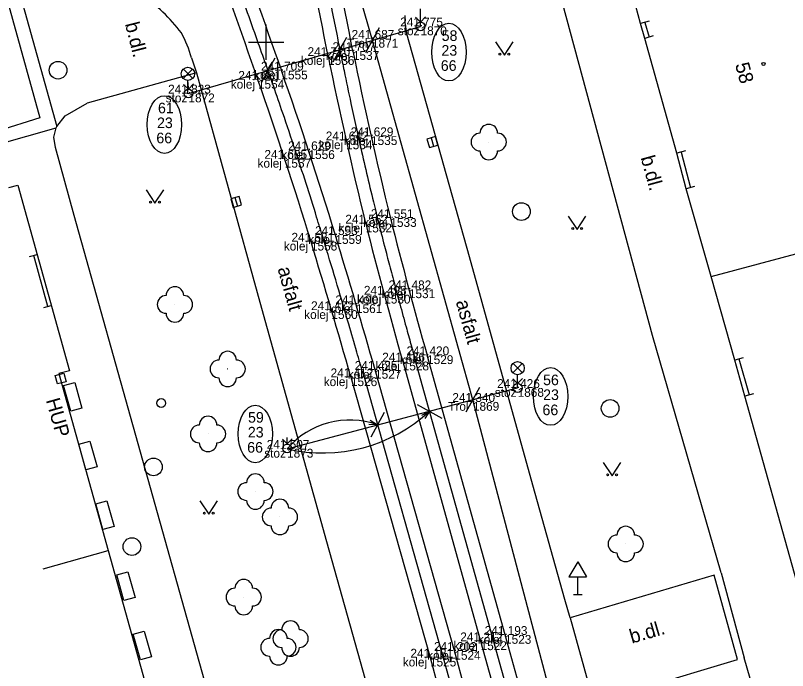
# Model space of a CAD drawing. Extents: x -599098 to -598820, y -1159597 to -1158744.
# Drawn here: x -599064.19 to -599020.49, y -1158835.58 to -1158798.48 of the extents above; entities that cross this region are included whole.
import ezdxf

# ---------------------------------------------------------------- set-up
doc = ezdxf.new("R2010")
doc.units = 0
for name, color, linetype in [('body', 7, 'Continuous'), ('budovy', 7, 'Continuous'), ('dopravní značky semafory', 7, 'Continuous'), ('druh pozemku stromy', 7, 'Continuous'), ('hektometrická síť', 7, 'Continuous'), ('kresba', 7, 'Continuous'), ('kódy bodů', 7, 'Continuous'), ('popisy', 7, 'Continuous'), ('popisy budov', 7, 'Continuous'), ('tram_koleje', 7, 'Continuous'), ('tram_osa', 7, 'Continuous'), ('trol_detaily', 7, 'Continuous'), ('trol_převěsy', 7, 'Continuous'), ('trol_troljová stopa', 7, 'Continuous'), ('trol_ved sloupy konzoly', 7, 'Continuous'), ('trol_čísla sloupů', 7, 'Continuous'), ('výšky bodů', 7, 'Continuous'), ('značky IS', 7, 'Continuous'), ('čísla bodů', 7, 'Continuous')]:
    doc.layers.add(name, color=color, linetype=linetype)

msp = doc.modelspace()

# ---------------------------------------------------------------- linework, layer by layer
at = {"layer": 'body'}
for p, q in [((-599041.262, -1158799.101), (-599041.262, -1158799.101)), ((-599044.013, -1158799.804), (-599044.013, -1158799.804)), ((-599045.09, -1158800.499), (-599045.09, -1158800.499)), ((-599046.492, -1158800.781), (-599046.492, -1158800.781)), ((-599049.138, -1158801.601), (-599049.138, -1158801.601)), ((-599050.466, -1158802.126), (-599050.466, -1158802.126)), ((-599054.399, -1158802.902), (-599054.399, -1158802.902)), ((-599044.063, -1158805.318), (-599044.063, -1158805.318)), ((-599045.476, -1158805.555), (-599045.476, -1158805.555)), ((-599047.604, -1158806.111), (-599047.604, -1158806.111)), ((-599048.947, -1158806.6), (-599048.947, -1158806.6)), ((-599044.368, -1158810.268), (-599044.368, -1158810.268)), ((-599042.97, -1158809.955), (-599042.97, -1158809.955)), ((-599046.082, -1158810.917), (-599046.082, -1158810.917)), ((-599047.462, -1158811.292), (-599047.462, -1158811.292)), ((-599041.921, -1158813.989), (-599041.921, -1158813.989)), ((-599043.318, -1158814.296), (-599043.318, -1158814.296)), ((-599044.915, -1158814.833), (-599044.915, -1158814.833)), ((-599046.306, -1158815.169), (-599046.306, -1158815.169)), ((-599040.891, -1158817.723), (-599040.891, -1158817.723)), ((-599042.271, -1158818.081), (-599042.271, -1158818.081)), ((-599043.835, -1158818.553), (-599043.835, -1158818.553)), ((-599045.202, -1158818.97), (-599045.202, -1158818.97)), ((-599035.767, -1158819.577), (-599035.767, -1158819.577)), ((-599038.296, -1158820.367), (-599038.296, -1158820.367)), ((-599048.818, -1158823.02), (-599048.818, -1158823.02)), ((-599037.862, -1158833.921), (-599037.862, -1158833.921)), ((-599036.478, -1158833.562), (-599036.478, -1158833.562)), ((-599039.348, -1158834.467), (-599039.348, -1158834.467)), ((-599040.727, -1158834.846), (-599040.727, -1158834.846))]:
    msp.add_line(p, q, dxfattribs=at)
at = {"layer": 'budovy'}
for p, q in [((-599028.81, -1158798.94), (-599029.62, -1158795.96)), ((-599028.57, -1158799.78), (-599028.81, -1158798.94)), ((-599026.75, -1158806.28), (-599028.57, -1158799.78)), ((-599026.23, -1158808.3), (-599026.75, -1158806.28)), ((-599064.56, -1158808.22), (-599064.06, -1158808.09)), ((-599064.06, -1158808.09), (-599061.14, -1158818.6)), ((-599024.82, -1158813.26), (-599026.23, -1158808.3)), ((-599024.82, -1158813.26), (-599018.089, -1158811.461)), ((-599023.48, -1158818), (-599024.82, -1158813.26)), ((-599022.9, -1158820.04), (-599023.48, -1158818)), ((-599061.14, -1158818.6), (-599061.73, -1158818.75)), ((-599061.73, -1158818.75), (-599058.94, -1158828.78)), ((-599019.84, -1158831.02), (-599022.9, -1158820.04)), ((-599062.618, -1158829.815), (-599058.94, -1158828.78)), ((-599058.94, -1158828.78), (-599054.26, -1158845.47))]:
    msp.add_line(p, q, dxfattribs=at)
msp.add_circle((-599021.85, -1158801.23), 0.0875, dxfattribs=at)
at = {"layer": 'dopravní značky semafory'}
for p, q in [((-599041.262, -1158799.101), (-599041.262, -1158798.101)), ((-599032.36, -1158829.414), (-599032.86, -1158830.28)), ((-599032.36, -1158829.414), (-599031.86, -1158830.28)), ((-599032.86, -1158830.28), (-599031.86, -1158830.28)), ((-599032.36, -1158831.28), (-599032.36, -1158830.28)), ((-599032.61, -1158831.28), (-599032.11, -1158831.28))]:
    msp.add_line(p, q, dxfattribs=at)
at = {"layer": 'druh pozemku stromy'}
for points in [[(-599037.018, -1158799.976), (-599036.518, -1158800.726), (-599036.018, -1158799.976)], [(-599056.795, -1158808.355), (-599056.295, -1158809.105), (-599055.795, -1158808.355)], [(-599032.897, -1158809.846), (-599032.397, -1158810.596), (-599031.897, -1158809.846)], [(-599030.922, -1158823.795), (-599030.422, -1158824.545), (-599029.922, -1158823.795)], [(-599053.749, -1158825.967), (-599053.249, -1158826.717), (-599052.749, -1158825.967)]]:
    msp.add_lwpolyline(points, dxfattribs=at)
for centre, radius in [((-599036.768, -1158800.676), 0.05), ((-599036.268, -1158800.676), 0.05), ((-599037.4, -1158805.65), 0.0005), ((-599056.545, -1158809.055), 0.05), ((-599056.045, -1158809.055), 0.05), ((-599032.647, -1158810.546), 0.05), ((-599032.147, -1158810.546), 0.05), ((-599055.167, -1158814.847), 0.0005), ((-599052.18, -1158818.5), 0.0005), ((-599053.29, -1158822.18), 0.0005), ((-599030.672, -1158824.495), 0.05), ((-599030.172, -1158824.495), 0.05), ((-599050.61, -1158825.44), 0.0005), ((-599053.499, -1158826.667), 0.05), ((-599052.999, -1158826.667), 0.05), ((-599049.22, -1158826.88), 0.0005), ((-599029.65, -1158828.41), 0.0005), ((-599051.27, -1158831.42), 0.0005), ((-599048.62, -1158833.77), 0.0005), ((-599049.31, -1158834.26), 0.0005)]:
    msp.add_circle(centre, radius, dxfattribs=at)
for centre, start, end in [((-599037.4, -1158805.15), 0, 180), ((-599037.9, -1158805.65), 90, 270), ((-599036.9, -1158805.65), 270, 90), ((-599037.4, -1158806.15), 180, 360), ((-599055.167, -1158814.347), 0, 180), ((-599055.667, -1158814.847), 90, 270), ((-599054.667, -1158814.847), 270, 90), ((-599055.167, -1158815.347), 180, 360), ((-599052.18, -1158818), 0, 180), ((-599052.68, -1158818.5), 90, 270), ((-599051.68, -1158818.5), 270, 90), ((-599052.18, -1158819), 180, 360), ((-599053.29, -1158821.68), 0, 180), ((-599053.79, -1158822.18), 90, 270), ((-599052.79, -1158822.18), 270, 90), ((-599053.29, -1158822.68), 180, 360), ((-599050.61, -1158824.94), 0, 180), ((-599051.11, -1158825.44), 90, 270), ((-599050.11, -1158825.44), 270, 90), ((-599050.61, -1158825.94), 180, 360), ((-599049.22, -1158826.38), 0, 180), ((-599049.72, -1158826.88), 90, 270), ((-599048.72, -1158826.88), 270, 90), ((-599049.22, -1158827.38), 180, 360), ((-599029.65, -1158827.91), 0, 180), ((-599030.15, -1158828.41), 90, 270), ((-599029.15, -1158828.41), 270, 90), ((-599029.65, -1158828.91), 180, 360), ((-599051.27, -1158830.92), 0, 180), ((-599051.77, -1158831.42), 90, 270), ((-599050.77, -1158831.42), 270, 90), ((-599051.27, -1158831.92), 180, 360), ((-599048.62, -1158833.27), 0, 180), ((-599049.31, -1158833.76), 0, 180), ((-599049.12, -1158833.77), 90, 270), ((-599048.12, -1158833.77), 270, 90), ((-599049.81, -1158834.26), 90, 270), ((-599048.81, -1158834.26), 270, 90), ((-599048.62, -1158834.27), 180, 360), ((-599049.31, -1158834.76), 180, 360)]:
    msp.add_arc(centre, 0.5, start, end, dxfattribs=at)
at = {"layer": 'hektometrická síť'}
for p, q in [((-599050, -1158801), (-599050, -1158799)), ((-599051, -1158800), (-599049, -1158800))]:
    msp.add_line(p, q, dxfattribs=at)
at = {"layer": 'kresba'}
for p, q in [((-599064.94, -1158796.55), (-599062.82, -1158804.27)), ((-599064.18, -1158796.38), (-599061.85, -1158804.77)), ((-599028.14, -1158816.61), (-599033.21, -1158797.85)), ((-599028.329, -1158798.803), (-599028.81, -1158798.94)), ((-599028.57, -1158798.871), (-599028.33, -1158799.711)), ((-599038.5, -1158812.15), (-599042.04, -1158799.52)), ((-599028.089, -1158799.643), (-599028.57, -1158799.78)), ((-599054.23, -1158800.89), (-599053.94, -1158801.73)), ((-599053.94, -1158801.73), (-599060.14, -1158803.45)), ((-599053.94, -1158801.73), (-599050.36, -1158814.72)), ((-599061.37, -1158804.16), (-599060.139, -1158803.454)), ((-599061.85, -1158804.77), (-599061.37, -1158804.16)), ((-599062.82, -1158804.27), (-599065.48, -1158805.11)), ((-599065.27, -1158805.8), (-599061.89, -1158804.85)), ((-599062.02, -1158805.38), (-599061.89, -1158804.85)), ((-599061.89, -1158804.85), (-599061.85, -1158804.77)), ((-599061.93, -1158805.96), (-599062.02, -1158805.38)), ((-599060.87, -1158809.81), (-599061.93, -1158805.96)), ((-599026.266, -1158806.155), (-599026.75, -1158806.28)), ((-599026.508, -1158806.218), (-599025.988, -1158808.238)), ((-599025.746, -1158808.175), (-599026.23, -1158808.3)), ((-599052.85, -1158838.43), (-599060.87, -1158809.81)), ((-599063.397, -1158812.133), (-599062.97, -1158812.014)), ((-599062.351, -1158814.956), (-599063.156, -1158812.066)), ((-599034.9, -1158825.08), (-599038.5, -1158812.15)), ((-599062.592, -1158815.023), (-599062.167, -1158814.905)), ((-599050.36, -1158814.72), (-599046.59, -1158828.27)), ((-599024.24, -1158830.05), (-599028.14, -1158816.61)), ((-599022.999, -1158817.863), (-599023.48, -1158818)), ((-599023.24, -1158817.932), (-599022.66, -1158819.972)), ((-599061.47, -1158819.43), (-599060.84, -1158819.26)), ((-599061.06, -1158820.89), (-599061.47, -1158819.43)), ((-599060.84, -1158819.26), (-599060.43, -1158820.72)), ((-599022.419, -1158819.903), (-599022.9, -1158820.04)), ((-599060.43, -1158820.72), (-599061.06, -1158820.89)), ((-599060.61, -1158822.76), (-599059.98, -1158822.59)), ((-599060.2, -1158824.22), (-599060.61, -1158822.76)), ((-599059.98, -1158822.59), (-599059.57, -1158824.05)), ((-599059.57, -1158824.05), (-599060.2, -1158824.22)), ((-599033.1, -1158831.56), (-599034.9, -1158825.08)), ((-599059.65, -1158826.13), (-599059.02, -1158825.96)), ((-599059.02, -1158825.96), (-599058.61, -1158827.42)), ((-599059.24, -1158827.59), (-599059.65, -1158826.13)), ((-599058.61, -1158827.42), (-599059.24, -1158827.59)), ((-599046.59, -1158828.27), (-599042.83, -1158841.62)), ((-599058.46, -1158830.16), (-599057.83, -1158829.99)), ((-599057.83, -1158829.99), (-599057.42, -1158831.45)), ((-599058.05, -1158831.62), (-599058.46, -1158830.16)), ((-599024.64, -1158830.17), (-599032.79, -1158832.59)), ((-599023.33, -1158834.96), (-599024.64, -1158830.17)), ((-599024.24, -1158830.05), (-599022.94, -1158834.85)), ((-599057.42, -1158831.45), (-599058.05, -1158831.62)), ((-599032.79, -1158832.59), (-599033.1, -1158831.56)), ((-599032.79, -1158832.59), (-599031.46, -1158837.38)), ((-599057.53, -1158833.51), (-599056.9, -1158833.34)), ((-599057.12, -1158834.97), (-599057.53, -1158833.51)), ((-599056.9, -1158833.34), (-599056.49, -1158834.8)), ((-599056.49, -1158834.8), (-599057.12, -1158834.97)), ((-599031.46, -1158837.38), (-599023.33, -1158834.96)), ((-599020.59, -1158843.13), (-599022.94, -1158834.85))]:
    msp.add_line(p, q, dxfattribs=at)
for centre, radius, start, end in [((-599062.719, -1158805.456), 9.927, 37.0843, 55.2434), ((-599038.178, -1158798.547), 3.982, 179.0288, 194.1351), ((-599060.224, -1158802.472), 6.2, 14.7823, 28.9596)]:
    msp.add_arc(centre, radius, start, end, dxfattribs=at)
at = {"layer": 'tram_koleje'}
for p, q in [((-599036.478, -1158833.562), (-599040.891, -1158817.723)), ((-599042.271, -1158818.081), (-599037.862, -1158833.921)), ((-599039.348, -1158834.467), (-599043.835, -1158818.553)), ((-599045.202, -1158818.97), (-599040.727, -1158834.846)), ((-599037.862, -1158833.921), (-599033.651, -1158849.046)), ((-599032.265, -1158848.671), (-599036.478, -1158833.562)), ((-599035.263, -1158849.128), (-599039.348, -1158834.467)), ((-599040.727, -1158834.846), (-599036.638, -1158849.522))]:
    msp.add_line(p, q, dxfattribs=at)
for centre, radius, start, end in [((-599536.84, -1158897.01), 501.131, 11.10372, 12.14061), ((-599529.595, -1158895.69), 492.338, 11.11461, 12.15891), ((-597210.712, -1158150.292), 1950.388, 199.246436, 199.507983), ((-597789.976, -1158353.746), 1337.864, 199.196739, 199.581422), ((-598824.298, -1158755.964), 225.239, 191.40389, 193.86919), ((-598821.824, -1158755.462), 229.194, 191.40431, 193.83485), ((-599267.683, -1158878.451), 231.664, 16.94892, 19.37397), ((-599269.435, -1158878.965), 232.059, 16.95482, 19.33652), ((-598780.621, -1158743.667), 272.026, 194.17207, 195.876), ((-598778.54, -1158743.346), 272.69, 194.13845, 195.82811), ((-599584.712, -1158973.565), 562.652, 15.99198, 16.80254), ((-599586.761, -1158974.205), 563.369, 15.99466, 16.80866)]:
    msp.add_arc(centre, radius, start, end, dxfattribs=at)
at = {"layer": 'tram_osa'}
for points in [[(-598998.482, -1158972.553), (-599001.612, -1158961.324), (-599004.755, -1158950.077), (-599007.858, -1158938.885), (-599009.243, -1158933.905), (-599010.468, -1158929.507), (-599013.278, -1158919.438), (-599013.649, -1158918.106), (-599016.803, -1158906.805), (-599019.981, -1158895.419), (-599022.632, -1158885.903), (-599025.83, -1158874.435), (-599028.989, -1158863.1), (-599032.097, -1158851.938), (-599032.958, -1158848.858), (-599037.17, -1158833.741), (-599041.581, -1158817.902)], [(-599044.518, -1158818.761), (-599040.037, -1158834.656), (-599035.95, -1158849.325), (-599035.019, -1158852.662), (-599031.892, -1158863.891), (-599028.72, -1158875.28), (-599025.529, -1158886.717), (-599022.874, -1158896.237), (-599019.714, -1158907.545), (-599016.534, -1158918.918), (-599016.338, -1158919.622), (-599013.47, -1158929.909), (-599012.317, -1158934.072), (-599010.723, -1158939.81), (-599007.63, -1158950.895), (-599004.503, -1158962.072), (-599001.36, -1158973.306)]]:
    msp.add_lwpolyline(points, dxfattribs=at)
for points in [[(-599050.226, -1158781.191), (-599049.779, -1158782.843), (-599049.26, -1158784.839), (-599048.908, -1158786.239), (-599048.459, -1158788.087), (-599047.812, -1158790.885), (-599047.609, -1158791.804), (-599047.116, -1158794.12), (-599046.807, -1158795.602), (-599046.534, -1158796.929), (-599046.277, -1158798.195), (-599045.991, -1158799.626), (-599045.791, -1158800.64), (-599045.594, -1158801.602), (-599045.202, -1158803.462), (-599044.904, -1158804.829), (-599044.69, -1158805.788), (-599044.317, -1158807.41), (-599043.931, -1158809.037), (-599043.782, -1158809.649), (-599043.669, -1158810.111), (-599043.304, -1158811.541), (-599043.022, -1158812.624), (-599042.724, -1158813.749), (-599042.438, -1158814.813), (-599042.08, -1158816.121), (-599041.806, -1158817.102), (-599041.581, -1158817.902)], [(-599044.518, -1158818.761), (-599044.868, -1158817.544), (-599045.327, -1158815.967), (-599045.725, -1158814.611), (-599046.408, -1158812.312), (-599046.772, -1158811.104), (-599047.143, -1158809.897), (-599047.745, -1158807.988), (-599048.359, -1158806.1), (-599049.061, -1158804.005), (-599049.575, -1158802.512), (-599050.57, -1158799.693), (-599051.212, -1158797.872), (-599051.881, -1158795.968), (-599052.492, -1158794.222), (-599053.195, -1158792.184), (-599053.706, -1158790.656), (-599054.07, -1158789.541), (-599054.412, -1158788.474), (-599055.062, -1158786.382), (-599055.575, -1158784.668), (-599055.829, -1158783.8), (-599056.112, -1158782.812)]]:
    msp.add_spline(points, degree=3, dxfattribs=at)
at = {"layer": 'trol_detaily'}
for p, q in [((-599043.606, -1158799.19), (-599044.376, -1158800.591)), ((-599045.448, -1158799.723), (-599046.219, -1158801.125)), ((-599049.512, -1158800.899), (-599050.282, -1158802.3)), ((-599037.926, -1158819.547), (-599038.696, -1158820.949)), ((-599041.449, -1158820.506), (-599040.048, -1158821.277)), ((-599043.313, -1158820.969), (-599044.083, -1158822.37)), ((-599041.198, -1158821.111), (-599040.749, -1158820.891)), ((-599040.749, -1158820.891), (-599041.028, -1158821.306)), ((-599043.698, -1158821.669), (-599044.197, -1158821.639)), ((-599044.115, -1158821.393), (-599043.698, -1158821.669))]:
    msp.add_line(p, q, dxfattribs=at)
for centre, radius, start, end in [((-599046.79, -1158814.349), 8.905, 256.8355, 312.7216), ((-599045.288, -1158826.02), 4.632, 69.9221, 139.635)]:
    msp.add_arc(centre, radius, start, end, dxfattribs=at)
at = {"layer": 'trol_převěsy'}
for p, q in [((-599054.399, -1158802.902), (-599041.262, -1158799.101)), ((-599048.818, -1158823.02), (-599035.767, -1158819.577))]:
    msp.add_line(p, q, dxfattribs=at)
at = {"layer": 'trol_troljová stopa'}
for p, q in [((-599043.991, -1158799.891), (-599045.552, -1158794.297)), ((-599038.311, -1158820.248), (-599043.991, -1158799.891)), ((-599032.143, -1158843.549), (-599038.311, -1158820.248))]:
    msp.add_line(p, q, dxfattribs=at)
at = {"layer": 'trol_ved sloupy konzoly'}
for p, q in [((-599041.265, -1158798.852), (-599041.271, -1158798.48)), ((-599041.265, -1158798.852), (-599041.54, -1158798.585)), ((-599041.265, -1158798.852), (-599040.979, -1158798.559)), ((-599054.402, -1158802.653), (-599054.677, -1158802.386)), ((-599054.402, -1158802.653), (-599054.408, -1158802.281)), ((-599054.402, -1158802.653), (-599054.116, -1158802.36)), ((-599035.77, -1158819.328), (-599036.045, -1158819.061)), ((-599035.77, -1158819.328), (-599035.776, -1158818.956)), ((-599035.77, -1158819.328), (-599035.484, -1158819.035)), ((-599048.809, -1158822.748), (-599049.084, -1158822.481)), ((-599048.809, -1158822.748), (-599048.815, -1158822.376)), ((-599048.809, -1158822.748), (-599048.523, -1158822.455))]:
    msp.add_line(p, q, dxfattribs=at)
for centre in [(-599041.261, -1158799.102), (-599054.398, -1158802.903), (-599035.766, -1158819.578), (-599048.805, -1158822.998)]:
    msp.add_circle(centre, 0.248, dxfattribs=at)
at = {"layer": 'trol_čísla sloupů'}
for centre in [(-599039.657, -1158800.559), (-599055.757, -1158804.659), (-599033.902, -1158820.057), (-599050.616, -1158822.178)]:
    msp.add_ellipse(centre, major_axis=(0, -1.633), ratio=0.595913, dxfattribs=at)
at = {"layer": 'značky IS'}
for p, q in [((-599054.693, -1158802.052), (-599054.165, -1158801.524)), ((-599054.157, -1158802.05), (-599054.685, -1158801.52)), ((-599054.429, -1158802.914), (-599054.429, -1158802.164)), ((-599040.658, -1158805.409), (-599040.522, -1158805.891)), ((-599051.768, -1158808.799), (-599051.632, -1158809.281)), ((-599036.031, -1158818.715), (-599035.503, -1158818.187)), ((-599035.495, -1158818.712), (-599036.023, -1158818.183)), ((-599061.94, -1158818.87), (-599061.46, -1158818.73)), ((-599061.81, -1158819.35), (-599061.94, -1158818.87)), ((-599061.46, -1158818.73), (-599061.33, -1158819.22)), ((-599035.767, -1158819.577), (-599035.767, -1158818.827)), ((-599061.33, -1158819.22), (-599061.81, -1158819.35))]:
    msp.add_line(p, q, dxfattribs=at)
for points in [[(-599040.899, -1158805.478), (-599040.764, -1158805.959), (-599040.282, -1158805.823), (-599040.417, -1158805.342)], [(-599052.009, -1158808.868), (-599051.874, -1158809.349), (-599051.392, -1158809.213), (-599051.527, -1158808.732)]]:
    msp.add_lwpolyline(points, close=True, dxfattribs=at)
for centre, radius in [((-599061.78, -1158801.58), 0.5), ((-599054.429, -1158801.789), 0.375), ((-599035.552, -1158809.586), 0.5), ((-599035.767, -1158818.452), 0.375), ((-599055.94, -1158820.43), 0.25), ((-599030.53, -1158820.73), 0.5), ((-599056.38, -1158824.05), 0.5), ((-599057.6, -1158828.56), 0.5)]:
    msp.add_circle(centre, radius, dxfattribs=at)

# ---------------------------------------------------------------- texts
at = {"layer": 'kódy bodů'}
for s, p in [('stoz', (-599042.552, -1158799.601)), ('Trol', (-599045.413, -1158800.304)), ('kolej', (-599046.63, -1158800.999)), ('kolej', (-599048.032, -1158801.281)), ('kolej', (-599050.678, -1158802.101)), ('kolej', (-599052.006, -1158802.626)), ('stoz', (-599055.689, -1158803.402)), ('kolej', (-599047.016, -1158806.055)), ('kolej', (-599045.603, -1158805.818)), ('kolej', (-599049.144, -1158806.611)), ('kolej', (-599050.487, -1158807.1)), ('kolej', (-599045.908, -1158810.768)), ('kolej', (-599044.51, -1158810.455)), ('kolej', (-599047.622, -1158811.417)), ('kolej', (-599049.002, -1158811.792)), ('kolej', (-599044.858, -1158814.796)), ('kolej', (-599043.461, -1158814.489)), ('kolej', (-599047.846, -1158815.669)), ('kolej', (-599046.455, -1158815.333)), ('kolej', (-599042.431, -1158818.223)), ('kolej', (-599043.811, -1158818.581)), ('kolej', (-599045.375, -1158819.053)), ('kolej', (-599046.742, -1158819.47)), ('stoz', (-599037.057, -1158820.077)), ('Trol', (-599039.696, -1158820.867)), ('stoz', (-599050.108, -1158823.52)), ('kolej', (-599039.402, -1158834.421)), ('kolej', (-599038.018, -1158834.062)), ('kolej', (-599042.267, -1158835.346)), ('kolej', (-599040.888, -1158834.967))]:
    msp.add_text(s, height=0.5, dxfattribs=at).set_placement(p)
at = {"layer": 'popisy'}
for s, rotation, p in [('b.dl.', 284.1309, (-599057.997, -1158798.957)), ('b.dl.', 285.3605, (-599028.81, -1158806.528)), ('asfalt', 285.5601, (-599049.363, -1158812.817)), ('asfalt', 285.5601, (-599039.275, -1158814.688)), ('HUP', 285.6639, (-599062.475, -1158820.266)), ('b.dl.', 16.3335, (-599029.301, -1158834.059))]:
    msp.add_text(s, height=0.8, rotation=rotation, dxfattribs=at).set_placement(p)
at = {"layer": 'popisy budov'}
msp.add_text('58', height=0.8, rotation=285.36, dxfattribs=at).set_placement((-599023.465, -1158801.261))
at = {"layer": 'trol_čísla sloupů'}
for s, p in [('58', (-599040.066, -1158799.922)), ('23', (-599040.079, -1158800.76)), ('66', (-599040.116, -1158801.619)), ('61', (-599056.124, -1158804.022)), ('23', (-599056.179, -1158804.86)), ('66', (-599056.216, -1158805.719)), ('56', (-599034.327, -1158819.42)), ('23', (-599034.323, -1158820.258)), ('66', (-599034.36, -1158821.117)), ('59', (-599051.027, -1158821.541)), ('23', (-599051.037, -1158822.379)), ('66', (-599051.074, -1158823.238))]:
    msp.add_text(s, height=0.6, dxfattribs=at).set_placement(p)
at = {"layer": 'výšky bodů'}
for s, p in [('241.775', (-599042.414, -1158799.101)), ('241.687', (-599045.165, -1158799.804)), ('241.720', (-599047.658, -1158800.781)), ('241.707', (-599046.242, -1158800.499)), ('241.709', (-599050.29, -1158801.601)), ('241.681', (-599051.574, -1158802.126)), ('241.823', (-599055.551, -1158802.902)), ('241.642', (-599046.628, -1158805.555)), ('241.629', (-599045.215, -1158805.318)), ('241.629', (-599048.756, -1158806.111)), ('241.605', (-599050.099, -1158806.6)), ('241.551', (-599044.078, -1158809.955)), ('241.562', (-599045.52, -1158810.268)), ('241.531', (-599048.57, -1158811.292)), ('241.553', (-599047.234, -1158810.917)), ('241.498', (-599044.47, -1158814.296)), ('241.482', (-599043.073, -1158813.989)), ('241.472', (-599047.458, -1158815.169)), ('241.490', (-599046.081, -1158814.833)), ('241.420', (-599042.057, -1158817.723)), ('241.436', (-599043.431, -1158818.081)), ('241.425', (-599044.987, -1158818.553)), ('241.412', (-599046.354, -1158818.97)), ('241.426', (-599036.927, -1158819.577)), ('241.340', (-599039.462, -1158820.367)), ('241.507', (-599049.97, -1158823.02)), ('241.193', (-599037.63, -1158833.562)), ('241.212', (-599039.014, -1158833.921)), ('241.181', (-599041.835, -1158834.846)), ('241.202', (-599040.5, -1158834.467))]:
    msp.add_text(s, height=0.5, dxfattribs=at).set_placement(p)
at = {"layer": 'čísla bodů'}
for s, p in [('1870', (-599041.262, -1158799.601)), ('1871', (-599044.013, -1158800.304)), ('1537', (-599045.09, -1158800.999)), ('1536', (-599046.492, -1158801.281)), ('1555', (-599049.138, -1158802.101)), ('1554', (-599050.466, -1158802.626)), ('1872', (-599054.399, -1158803.402)), ('1535', (-599044.063, -1158805.818)), ('1534', (-599045.476, -1158806.055)), ('1556', (-599047.604, -1158806.611)), ('1557', (-599048.947, -1158807.1)), ('1532', (-599044.368, -1158810.768)), ('1533', (-599042.97, -1158810.455)), ('1559', (-599046.082, -1158811.417)), ('1558', (-599047.462, -1158811.792)), ('1531', (-599041.921, -1158814.489)), ('1530', (-599043.318, -1158814.796)), ('1561', (-599044.915, -1158815.333)), ('1560', (-599046.306, -1158815.669)), ('1529', (-599040.891, -1158818.223)), ('1528', (-599042.271, -1158818.581)), ('1527', (-599043.835, -1158819.053)), ('1526', (-599045.202, -1158819.47)), ('1868', (-599035.767, -1158820.077)), ('1869', (-599038.296, -1158820.867)), ('1873', (-599048.818, -1158823.52)), ('1522', (-599037.862, -1158834.421)), ('1523', (-599036.478, -1158834.062)), ('1524', (-599039.348, -1158834.967)), ('1525', (-599040.727, -1158835.346))]:
    msp.add_text(s, height=0.5, dxfattribs=at).set_placement(p)

doc.saveas('drawing.dxf')
